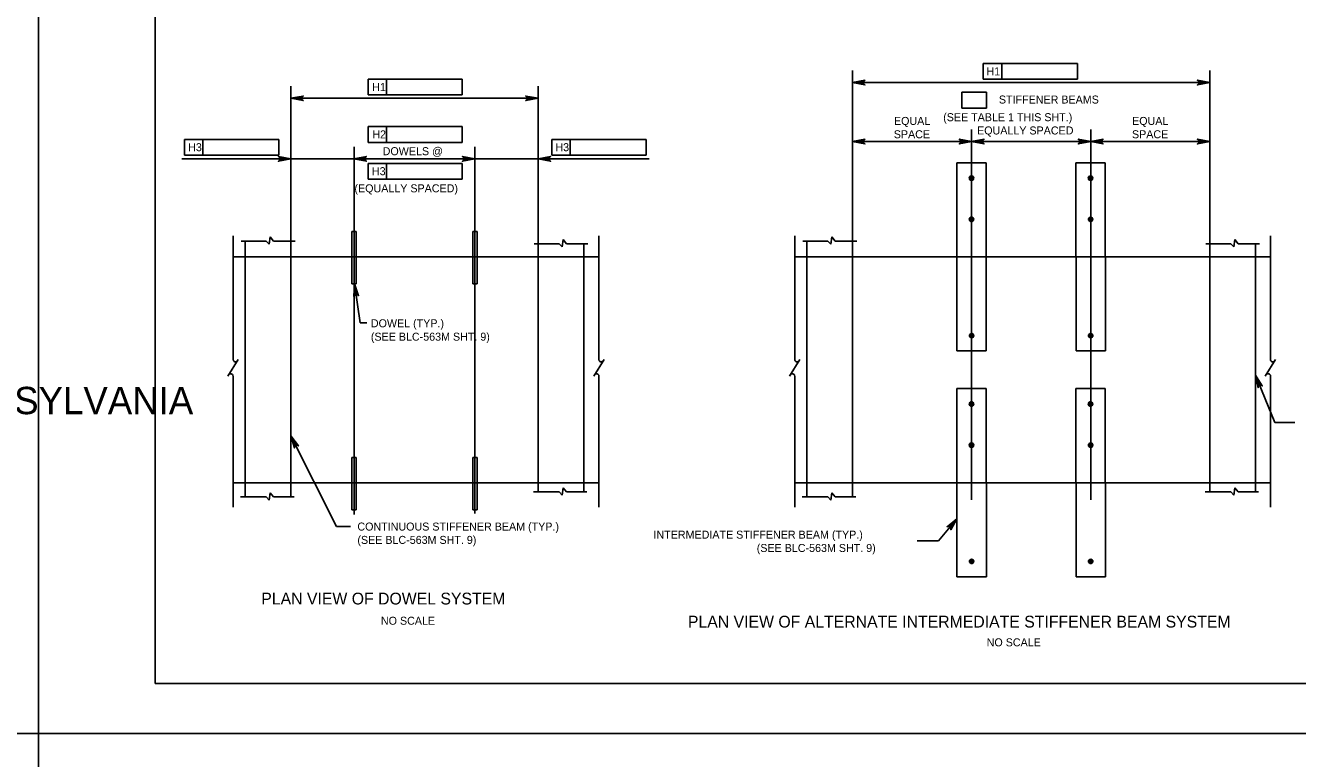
# Model space of a CAD drawing. Extents: x -8 to 75, y -110 to 0.
# Drawn here: x 33.8 to 52.87, y -44.38 to -33.38 of the extents above; entities that cross this region are included whole.
import ezdxf

# ---------------------------------------------------------------- set-up
doc = ezdxf.new("R2010")
doc.units = 0
for name, color, linetype in [('1', 7, 'Continuous'), ('2', 7, 'Continuous'), ('3', 7, 'Continuous'), ('4', 7, 'Continuous'), ('62', 7, 'Continuous'), ('63', 7, 'Continuous')]:
    doc.layers.add(name, color=color, linetype=linetype)

# ---------------------------------------------------------------- blocks, each defined once
blk = doc.blocks.new('D')
at = {"layer": '3'}
for p, q in [((-0.324, 0.383), (-0.383, 0.324)), ((0.349, -0.408), (-0.383, 0.324)), ((0.408, -0.349), (-0.324, 0.383)), ((0.408, -0.349), (0.349, -0.408))]:
    blk.add_line(p, q, dxfattribs=at)

msp = doc.modelspace()

# ---------------------------------------------------------------- linework, layer by layer
at = {"layer": '1'}
msp.add_lwpolyline([(35.75, -43.25), (67.25, -43.25), (67.25, -22.75), (35.75, -22.75)], close=True, dxfattribs=at)
at = {"layer": '2'}
for p, q in [((42.4, -36.848), (36.917, -36.848)), ((52.469, -36.848), (45.338, -36.848)), ((42.4, -40.236), (36.917, -40.236)), ((52.469, -40.236), (45.338, -40.236))]:
    msp.add_line(p, q, dxfattribs=at)
at = {"layer": '3'}
for p, q in [((47.765, -35.436), (47.767, -38.259)), ((48.206, -35.436), (47.765, -35.436)), ((48.206, -35.436), (48.208, -38.259)), ((49.55, -35.436), (49.553, -38.259)), ((49.991, -35.436), (49.55, -35.436)), ((49.991, -35.436), (49.994, -38.259)), ((36.917, -36.532), (36.917, -38.386)), ((37.036, -36.61), (37.413, -36.61)), ((37.097, -40.447), (37.097, -36.61)), ((37.413, -36.61), (37.456, -36.659)), ((37.456, -36.659), (37.473, -36.549)), ((37.473, -36.549), (37.521, -36.61)), ((37.521, -36.61), (37.845, -36.61)), ((37.782, -36.61), (37.782, -40.447)), ((41.849, -36.699), (41.866, -36.588)), ((41.866, -36.588), (41.913, -36.65)), ((42.4, -36.532), (42.4, -38.386)), ((45.338, -36.532), (45.338, -38.386)), ((45.456, -36.61), (45.833, -36.61)), ((45.518, -40.447), (45.518, -36.61)), ((45.833, -36.61), (45.877, -36.659)), ((45.877, -36.659), (45.894, -36.549)), ((45.894, -36.549), (45.941, -36.61)), ((45.941, -36.61), (46.265, -36.61)), ((46.203, -36.61), (46.203, -40.447)), ((51.918, -36.699), (51.935, -36.588)), ((51.935, -36.588), (51.982, -36.65)), ((52.469, -36.532), (52.469, -38.386)), ((41.428, -36.65), (41.805, -36.65)), ((41.49, -40.375), (41.49, -36.65)), ((41.805, -36.65), (41.849, -36.699)), ((41.913, -36.65), (42.237, -36.65)), ((42.175, -36.65), (42.175, -40.375)), ((51.497, -36.65), (51.874, -36.65)), ((51.559, -40.375), (51.559, -36.65)), ((51.874, -36.65), (51.918, -36.699)), ((51.982, -36.65), (52.306, -36.65)), ((52.244, -36.65), (52.244, -40.375)), ((38.698, -36.848), (38.761, -36.848)), ((40.511, -36.848), (40.574, -36.848)), ((48.208, -38.259), (47.767, -38.259)), ((49.994, -38.259), (49.553, -38.259)), ((36.995, -38.389), (36.84, -38.635)), ((42.477, -38.389), (42.323, -38.635)), ((45.415, -38.389), (45.26, -38.635)), ((52.546, -38.389), (52.391, -38.635)), ((36.917, -38.635), (36.917, -40.601)), ((42.4, -38.635), (42.4, -40.601)), ((45.338, -38.635), (45.338, -40.601)), ((52.469, -38.635), (52.469, -40.601)), ((47.765, -38.824), (47.767, -41.647)), ((48.206, -38.824), (47.765, -38.824)), ((48.206, -38.824), (48.209, -41.647)), ((49.991, -38.824), (49.55, -38.824)), ((49.55, -38.824), (49.553, -41.647)), ((49.991, -38.824), (49.994, -41.647)), ((38.698, -40.236), (38.761, -40.236)), ((40.511, -40.236), (40.574, -40.236)), ((37.456, -40.496), (37.473, -40.386)), ((37.473, -40.386), (37.521, -40.447)), ((41.421, -40.375), (41.805, -40.375)), ((41.805, -40.375), (41.849, -40.423)), ((41.849, -40.423), (41.866, -40.313)), ((41.866, -40.313), (41.913, -40.375)), ((41.913, -40.375), (42.222, -40.375)), ((45.877, -40.496), (45.894, -40.386)), ((45.894, -40.386), (45.941, -40.447)), ((51.49, -40.375), (51.874, -40.375)), ((51.874, -40.375), (51.918, -40.423)), ((51.918, -40.423), (51.935, -40.313)), ((51.935, -40.313), (51.982, -40.375)), ((51.982, -40.375), (52.291, -40.375)), ((37.028, -40.447), (37.413, -40.447)), ((37.413, -40.447), (37.456, -40.496)), ((37.521, -40.447), (37.83, -40.447)), ((45.448, -40.447), (45.833, -40.447)), ((45.833, -40.447), (45.877, -40.496)), ((45.941, -40.447), (46.25, -40.447)), ((48.209, -41.647), (47.767, -41.647)), ((49.994, -41.647), (49.553, -41.647))]:
    msp.add_line(p, q, dxfattribs=at)
for centre, radius in [((47.986, -35.666), 0.0333), ((47.986, -35.666), 0.0295), ((47.986, -35.666), 0.025), ((47.986, -35.666), 0.0167), ((47.986, -35.666), 0.00833), ((49.771, -35.666), 0.0333), ((49.771, -35.666), 0.0295), ((49.771, -35.666), 0.025), ((49.771, -35.666), 0.0167), ((49.771, -35.666), 0.00833), ((47.986, -36.285), 0.0333), ((47.986, -36.285), 0.0295), ((47.986, -36.285), 0.025), ((47.986, -36.285), 0.0167), ((47.986, -36.285), 0.00833), ((49.772, -36.285), 0.0333), ((49.772, -36.285), 0.0295), ((49.772, -36.285), 0.025), ((49.772, -36.285), 0.0167), ((49.772, -36.285), 0.00833), ((47.988, -38.029), 0.0333), ((47.988, -38.029), 0.0295), ((47.988, -38.029), 0.025), ((47.988, -38.029), 0.0167), ((47.988, -38.029), 0.00833), ((49.773, -38.029), 0.0333), ((49.773, -38.029), 0.0295), ((49.773, -38.029), 0.025), ((49.773, -38.029), 0.0167), ((49.773, -38.029), 0.00833), ((47.986, -39.055), 0.0333), ((47.986, -39.055), 0.0295), ((47.986, -39.055), 0.025), ((47.986, -39.055), 0.0167), ((47.986, -39.055), 0.00833), ((49.771, -39.055), 0.0333), ((49.771, -39.055), 0.0295), ((49.771, -39.055), 0.025), ((49.771, -39.055), 0.0167), ((49.771, -39.055), 0.00833), ((47.986, -39.673), 0.0333), ((47.986, -39.673), 0.0295), ((47.986, -39.673), 0.025), ((47.986, -39.673), 0.0167), ((47.986, -39.673), 0.00833), ((49.772, -39.673), 0.0333), ((49.772, -39.673), 0.0295), ((49.772, -39.673), 0.025), ((49.772, -39.673), 0.0167), ((49.772, -39.673), 0.00833), ((47.988, -41.417), 0.0333), ((49.773, -41.417), 0.0333), ((47.988, -41.417), 0.0295), ((47.988, -41.417), 0.025), ((47.988, -41.417), 0.0167), ((47.988, -41.417), 0.00833), ((49.773, -41.417), 0.0295), ((49.773, -41.417), 0.025), ((49.773, -41.417), 0.0167), ((49.773, -41.417), 0.00833)]:
    msp.add_circle(centre, radius, dxfattribs=at)
for centre, start, end in [((36.954, -38.386), 180, 330), ((42.436, -38.386), 180, 330), ((45.374, -38.386), 180, 330), ((52.505, -38.386), 180, 330), ((36.881, -38.638), 5.3286, 147.8672), ((42.364, -38.638), 5.3286, 147.8672), ((45.301, -38.638), 5.3286, 147.8672), ((52.433, -38.638), 5.3286, 147.8672)]:
    msp.add_arc(centre, 0.0364, start, end, dxfattribs=at)
at = {"layer": '4'}
for p, q in [((48.163, -33.944), (48.163, -34.18)), ((48.163, -33.944), (49.575, -33.944)), ((48.439, -33.944), (48.439, -34.18)), ((49.575, -33.944), (49.575, -34.18)), ((46.203, -36.412), (46.203, -34.053)), ((51.559, -36.455), (51.559, -34.053)), ((37.782, -37.048), (37.782, -34.288)), ((38.941, -34.179), (40.353, -34.179)), ((38.941, -34.179), (38.941, -34.416)), ((39.216, -34.179), (39.216, -34.416)), ((40.353, -34.179), (40.353, -34.416)), ((41.49, -36.723), (41.49, -34.288)), ((51.559, -34.233), (46.203, -34.233)), ((49.575, -34.18), (48.163, -34.18)), ((41.49, -34.468), (37.782, -34.468)), ((40.353, -34.416), (38.941, -34.416)), ((47.84, -34.377), (48.211, -34.377)), ((47.84, -34.377), (47.84, -34.614)), ((48.211, -34.377), (48.211, -34.614)), ((48.211, -34.614), (47.84, -34.614)), ((38.941, -34.894), (38.941, -35.13)), ((38.941, -34.894), (40.353, -34.894)), ((39.216, -34.894), (39.216, -35.13)), ((40.353, -34.894), (40.353, -35.13)), ((36.19, -35.086), (37.602, -35.086)), ((36.19, -35.086), (36.19, -35.322)), ((36.465, -35.086), (36.465, -35.322)), ((37.602, -35.086), (37.602, -35.322)), ((41.695, -35.086), (43.107, -35.086)), ((41.695, -35.086), (41.695, -35.322)), ((41.971, -35.086), (41.971, -35.322)), ((43.107, -35.086), (43.107, -35.322)), ((46.203, -36.785), (46.203, -34.939)), ((47.988, -40.495), (47.988, -34.939)), ((49.773, -40.495), (49.773, -34.939)), ((51.559, -36.785), (51.559, -34.939)), ((37.782, -36.785), (37.782, -35.197)), ((38.73, -40.715), (38.73, -35.197)), ((40.353, -35.13), (38.941, -35.13)), ((40.543, -40.7), (40.543, -35.197)), ((41.49, -36.785), (41.49, -35.197)), ((47.868, -35.119), (46.203, -35.119)), ((49.653, -35.119), (48.108, -35.119)), ((49.893, -35.119), (51.559, -35.119)), ((37.662, -35.377), (36.147, -35.377)), ((37.602, -35.322), (36.19, -35.322)), ((38.729, -35.377), (37.781, -35.377)), ((40.422, -35.377), (38.849, -35.377)), ((38.941, -35.445), (40.353, -35.445)), ((38.941, -35.445), (38.941, -35.682)), ((39.216, -35.445), (39.216, -35.682)), ((40.422, -35.377), (40.302, -35.377)), ((40.353, -35.445), (40.353, -35.682)), ((41.49, -35.377), (40.542, -35.377)), ((41.61, -35.377), (43.153, -35.377)), ((43.107, -35.322), (41.695, -35.322)), ((40.353, -35.682), (38.941, -35.682)), ((38.82, -37.835), (38.738, -37.251)), ((38.92, -37.835), (38.82, -37.835)), ((52.533, -39.334), (52.832, -39.334)), ((37.782, -39.533), (38.466, -40.892)), ((47.49, -41.108), (47.767, -40.777)), ((38.466, -40.892), (38.675, -40.892)), ((47.17, -41.108), (47.49, -41.108))]:
    msp.add_line(p, q, dxfattribs=at)
for points in [[(46.203, -34.233), (46.389, -34.198), (46.375, -34.208), (46.367, -34.221), (46.365, -34.233), (46.367, -34.245), (46.375, -34.258), (46.389, -34.268), (46.203, -34.233), (46.375, -34.258), (46.367, -34.245), (46.203, -34.233), (46.365, -34.233), (46.367, -34.221), (46.203, -34.233), (46.375, -34.208)], [(51.559, -34.233), (51.372, -34.268), (51.387, -34.258), (51.394, -34.245), (51.396, -34.233), (51.394, -34.221), (51.387, -34.208), (51.372, -34.198), (51.559, -34.233), (51.387, -34.208), (51.394, -34.221), (51.559, -34.233), (51.396, -34.233), (51.394, -34.245), (51.559, -34.233), (51.387, -34.258)], [(37.782, -34.468), (37.969, -34.434), (37.954, -34.443), (37.947, -34.456), (37.945, -34.468), (37.947, -34.481), (37.954, -34.493), (37.969, -34.503), (37.782, -34.468), (37.954, -34.493), (37.947, -34.481), (37.782, -34.468), (37.945, -34.468), (37.947, -34.456), (37.782, -34.468), (37.954, -34.443)], [(41.49, -34.468), (41.303, -34.503), (41.318, -34.493), (41.325, -34.481), (41.327, -34.468), (41.325, -34.456), (41.318, -34.443), (41.303, -34.434), (41.49, -34.468), (41.318, -34.443), (41.325, -34.456), (41.49, -34.468), (41.327, -34.468), (41.325, -34.481), (41.49, -34.468), (41.318, -34.493)], [(46.203, -35.119), (46.389, -35.084), (46.375, -35.094), (46.367, -35.106), (46.365, -35.119), (46.367, -35.131), (46.375, -35.144), (46.389, -35.154), (46.203, -35.119), (46.375, -35.144), (46.367, -35.131), (46.203, -35.119), (46.365, -35.119), (46.367, -35.106), (46.203, -35.119), (46.375, -35.094)], [(47.988, -35.119), (47.802, -35.154), (47.816, -35.144), (47.823, -35.131), (47.825, -35.119), (47.823, -35.106), (47.816, -35.094), (47.802, -35.084), (47.988, -35.119), (47.816, -35.094), (47.823, -35.106), (47.988, -35.119), (47.825, -35.119), (47.823, -35.131), (47.988, -35.119), (47.816, -35.144)], [(47.988, -35.119), (48.174, -35.154), (48.16, -35.144), (48.153, -35.131), (48.151, -35.119), (48.153, -35.106), (48.16, -35.094), (48.174, -35.084), (47.988, -35.119), (48.16, -35.094), (48.153, -35.106), (47.988, -35.119), (48.151, -35.119), (48.153, -35.131), (47.988, -35.119), (48.16, -35.144)], [(49.773, -35.119), (49.587, -35.154), (49.601, -35.144), (49.609, -35.131), (49.611, -35.119), (49.609, -35.106), (49.601, -35.094), (49.587, -35.084), (49.773, -35.119), (49.601, -35.094), (49.609, -35.106), (49.773, -35.119), (49.611, -35.119), (49.609, -35.131), (49.773, -35.119), (49.601, -35.144)], [(49.773, -35.119), (49.96, -35.154), (49.945, -35.144), (49.938, -35.131), (49.936, -35.119), (49.938, -35.106), (49.945, -35.094), (49.96, -35.084), (49.773, -35.119), (49.945, -35.094), (49.938, -35.106), (49.773, -35.119), (49.936, -35.119), (49.938, -35.131), (49.773, -35.119), (49.945, -35.144)], [(51.559, -35.119), (51.372, -35.154), (51.387, -35.144), (51.394, -35.131), (51.396, -35.119), (51.394, -35.106), (51.387, -35.094), (51.372, -35.084), (51.559, -35.119), (51.387, -35.094), (51.394, -35.106), (51.559, -35.119), (51.396, -35.119), (51.394, -35.131), (51.559, -35.119), (51.387, -35.144)], [(37.782, -35.377), (37.596, -35.412), (37.61, -35.402), (37.618, -35.389), (37.62, -35.377), (37.618, -35.364), (37.61, -35.352), (37.596, -35.342), (37.782, -35.377), (37.61, -35.352), (37.618, -35.364), (37.782, -35.377), (37.62, -35.377), (37.618, -35.389), (37.782, -35.377), (37.61, -35.402)], [(38.729, -35.377), (38.916, -35.342), (38.901, -35.352), (38.894, -35.364), (38.892, -35.377), (38.894, -35.389), (38.901, -35.402), (38.916, -35.412), (38.729, -35.377), (38.901, -35.402), (38.894, -35.389), (38.729, -35.377), (38.892, -35.377), (38.894, -35.364), (38.729, -35.377), (38.901, -35.352)], [(40.542, -35.377), (40.355, -35.412), (40.37, -35.402), (40.377, -35.389), (40.379, -35.377), (40.377, -35.364), (40.37, -35.352), (40.355, -35.342), (40.542, -35.377), (40.37, -35.352), (40.377, -35.364), (40.542, -35.377), (40.379, -35.377), (40.377, -35.389), (40.542, -35.377), (40.37, -35.402)], [(41.49, -35.377), (41.676, -35.342), (41.662, -35.352), (41.655, -35.364), (41.652, -35.377), (41.655, -35.389), (41.662, -35.402), (41.676, -35.412), (41.49, -35.377), (41.662, -35.402), (41.655, -35.389), (41.49, -35.377), (41.652, -35.377), (41.655, -35.364), (41.49, -35.377), (41.662, -35.352)], [(38.738, -37.251), (38.798, -37.431), (38.787, -37.418), (38.773, -37.412), (38.761, -37.412), (38.748, -37.416), (38.737, -37.425), (38.729, -37.441), (38.738, -37.251), (38.737, -37.425), (38.748, -37.416), (38.738, -37.251), (38.761, -37.412), (38.773, -37.412), (38.738, -37.251), (38.787, -37.418)], [(52.244, -38.624), (52.533, -39.334)], [(52.244, -38.624), (52.346, -38.784), (52.332, -38.774), (52.317, -38.772), (52.305, -38.775), (52.294, -38.782), (52.286, -38.793), (52.282, -38.81), (52.244, -38.624), (52.286, -38.793), (52.294, -38.782), (52.244, -38.624), (52.305, -38.775), (52.317, -38.772), (52.244, -38.624), (52.332, -38.774)], [(37.782, -39.533), (37.897, -39.684), (37.882, -39.675), (37.867, -39.674), (37.855, -39.678), (37.845, -39.685), (37.837, -39.698), (37.835, -39.715), (37.782, -39.533), (37.837, -39.698), (37.845, -39.685), (37.782, -39.533), (37.855, -39.678), (37.867, -39.674), (37.782, -39.533), (37.882, -39.675)], [(47.767, -40.777), (47.674, -40.942), (47.676, -40.925), (47.671, -40.911), (47.663, -40.901), (47.652, -40.895), (47.637, -40.893), (47.621, -40.897), (47.767, -40.777), (47.637, -40.893), (47.652, -40.895), (47.767, -40.777), (47.663, -40.901), (47.671, -40.911), (47.767, -40.777), (47.676, -40.925)]]:
    msp.add_lwpolyline(points, dxfattribs=at)
for points in [[(46.323, -34.213), (46.323, -34.253), (46.203, -34.233)], [(51.439, -34.213), (51.439, -34.253), (51.559, -34.233)], [(37.902, -34.448), (37.902, -34.488), (37.782, -34.468)], [(41.37, -34.448), (41.37, -34.488), (41.49, -34.468)], [(46.323, -35.099), (46.323, -35.139), (46.203, -35.119)], [(47.868, -35.099), (47.868, -35.139), (47.988, -35.119)], [(48.108, -35.099), (48.108, -35.139), (47.988, -35.119)], [(49.653, -35.099), (49.653, -35.139), (49.773, -35.119)], [(49.893, -35.099), (49.893, -35.139), (49.773, -35.119)], [(51.439, -35.099), (51.439, -35.139), (51.559, -35.119)], [(37.662, -35.357), (37.662, -35.397), (37.782, -35.377)], [(38.849, -35.357), (38.849, -35.397), (38.729, -35.377)], [(40.422, -35.357), (40.422, -35.397), (40.542, -35.377)], [(41.61, -35.357), (41.61, -35.397), (41.49, -35.377)], [(52.244, -38.624), (52.28, -38.739), (52.298, -38.732)]]:
    msp.add_lwpolyline(points, close=True, dxfattribs=at)
at = {"layer": '62'}
msp.add_line((34, -44), (34, -44), dxfattribs=at)
at = {"layer": '63'}
for points in [[(0, -44), (34, -44), (34, -22), (0, -22)], [(34, -44), (68, -44), (68, -22), (34, -22)], [(0, -66), (34, -66), (34, -44), (0, -44)], [(34, -66), (68, -66), (68, -44), (34, -44)]]:
    msp.add_lwpolyline(points, close=True, dxfattribs=at)

# ---------------------------------------------------------------- block references
at = {"layer": '4', "xscale": 0.7559417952, "yscale": 0.7559417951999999, "rotation": -44.99995150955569}
for p in [(38.729, -36.847), (40.542, -36.847), (38.729, -40.236), (40.542, -40.236)]:
    msp.add_blockref('D', p, dxfattribs=at)

# ---------------------------------------------------------------- texts
at = {"layer": '1'}
msp.add_text('COMMONWEALTH OF PENNSYLVANIA', height=0.41038, dxfattribs=at).set_placement((26.196, -39.208))
at = {"layer": '4'}
for s, height, p in [('H1', 0.12, (48.21, -34.125)), ('H1', 0.12, (39.001, -34.361)), ('STIFFENER BEAMS', 0.12, (48.397, -34.547)), ('(SEE TABLE 1 THIS SHT.)', 0.12, (47.562, -34.812)), ('EQUAL', 0.12, (46.824, -34.868)), ('EQUALLY SPACED', 0.12, (48.07, -35.011)), ('EQUAL', 0.12, (50.394, -34.868)), ('H2', 0.12, (39.004, -35.07)), ('SPACE', 0.12, (46.821, -35.068)), ('SPACE', 0.12, (50.392, -35.068)), ('H3', 0.12, (36.243, -35.262)), ('DOWELS @', 0.12, (39.159, -35.322)), ('H3', 0.12, (41.748, -35.262)), ('H3', 0.12, (38.998, -35.622)), ('(EQUALLY SPACED)', 0.12, (38.736, -35.879)), ('DOWEL (TYP.)', 0.12, (38.982, -37.904)), ('(SEE BLC-563M SHT. 9)', 0.12, (38.982, -38.105)), ('CONTINUOUS STIFFENER BEAM (TYP.)', 0.12, (38.78, -40.954)), ('INTERMEDIATE STIFFENER BEAM (TYP.)', 0.12, (43.219, -41.075)), ('(SEE BLC-563M SHT. 9)', 0.12, (38.78, -41.154)), ('(SEE BLC-563M SHT. 9)', 0.12, (44.767, -41.275)), ('PLAN VIEW OF DOWEL SYSTEM', 0.17717, (37.339, -42.063)), ('NO SCALE', 0.12, (39.133, -42.367)), ('PLAN VIEW OF ALTERNATE INTERMEDIATE STIFFENER BEAM SYSTEM', 0.17717, (43.735, -42.409)), ('NO SCALE', 0.12, (48.214, -42.691))]:
    msp.add_text(s, height=height, dxfattribs=at).set_placement(p)

doc.saveas('drawing.dxf')
